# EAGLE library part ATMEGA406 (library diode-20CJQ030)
ATMEL's ATmega406 8bit AVR Microcontroller with 40KB In-System Programmable Flash Summary : Previous implementations of intelligent battery protection have typically required at least two chips to perform the various tasks required which include: voltage regulation, battery monitoring, battery protection, charge management, and communication with the host application. Often a third chip has been required to store parameters specific to the particular battery. Battery packs must shrink in size along with the other components of battery-powered applications. However, when accelerating this shrink, a 3-chip solution obviously creates a PCB space problem. The ATmega406 meets all the application's demands, reducing space, design complexity, and ultimately cost. It includes an AVR® microcontroller with dedicated analog to digital converters tailored for battery fuel gauging and voltage monitoring. Also included are stand-alone high voltage battery protection circuitry, a voltage regulator capable of running the chip on a supply varying from 4 to 25 Volts, integrated cell balancing FETs, and special high voltage I/O capable of controlling charge and discharge. Advanced analog design provides the ATmega406 with unmatched on-chip voltage reference accuracy, resulting in the first single-chip smart battery implementation on the market for 2 - 4 Li-ion cells. With 40 KB of self-programmable Flash program memory, the ATmega406 is capable of in-field firmware upgrades without the need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
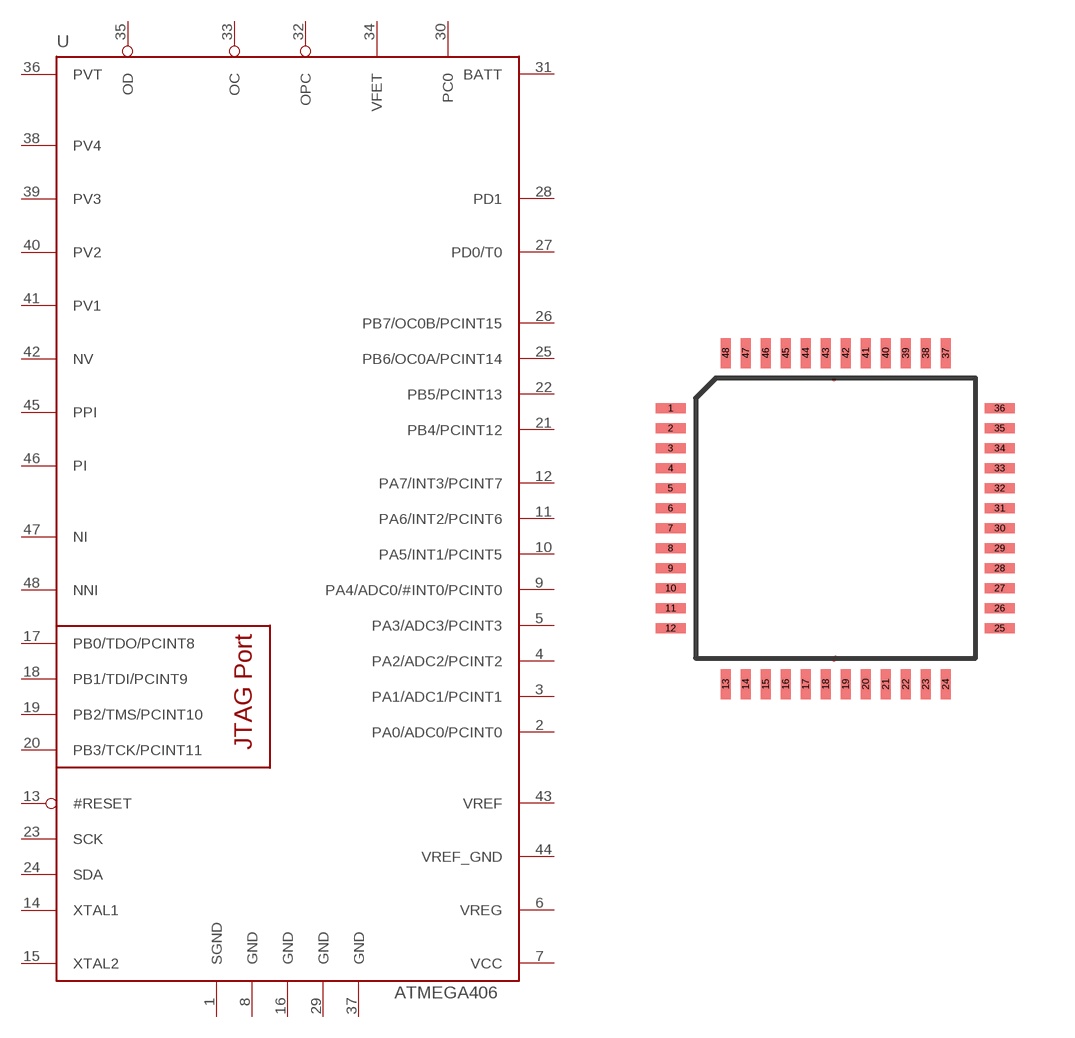
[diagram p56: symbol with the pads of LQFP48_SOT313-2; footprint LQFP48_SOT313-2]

Designator prefix U

## ATMEGA406  [LQFP48_SOT313-2]
1  SGND  pwr
2  PA0/ADC0/PCINT0
3  PA1/ADC1/PCINT1
4  PA2/ADC2/PCINT2
5  PA3/ADC3/PCINT3
6  VREG  out
7  VCC  pwr
8  GND  pwr
9  PA4/ADC0/#INT0/PCINT0
10  PA5/INT1/PCINT5
11  PA6/INT2/PCINT6
12  PA7/INT3/PCINT7
13  #RESET  in
14  XTAL1  in
15  XTAL2  in
16  GND  pwr
17  PB0/TDO/PCINT8
18  PB1/TDI/PCINT9
19  PB2/TMS/PCINT10
20  PB3/TCK/PCINT11
21  PB4/PCINT12
22  PB5/PCINT13
23  SCK
24  SDA
25  PB6/OC0A/PCINT14
26  PB7/OC0B/PCINT15
27  PD0/T0
28  PD1
29  GND  pwr
30  PC0  out
31  BATT  in
32  OPC  out
33  OC  out
34  VFET  pwr
35  OD  out
36  PVT  in
37  GND  pwr
38  PV4  in
39  PV3  in
40  PV2  in
41  PV1  in
42  NV  in
43  VREF  pwr
44  VREF_GND  pwr
45  PPI  in
46  PI  in
47  NI  in
48  NNI  in

## Footprint LQFP48_SOT313-2 (pad centres in mm)
LQFP48: plastic low profile quad flat package 48 leads body 7 x 7 x 1.4 mm
smd 0.75 x 0.25: 1 -4.125,2.75; 2 -4.125,2.25; 3 -4.125,1.75; 4 -4.125,1.25; 5 -4.125,0.75; 6 -4.125,0.25; 7 -4.125,-0.25; 8 -4.125,-0.75; 9 -4.125,-1.25; 10 -4.125,-1.75; 11 -4.125,-2.25; 12 -4.125,-2.75; 25 4.105,-2.75; 26 4.105,-2.25; 27 4.105,-1.75; 28 4.105,-1.25; 29 4.105,-0.75; 30 4.105,-0.25; 31 4.105,0.25; 32 4.105,0.75; 33 4.105,1.25; 34 4.105,1.75; 35 4.105,2.25; 36 4.105,2.75
smd 0.25 x 0.75: 13 -2.75,-4.155; 14 -2.25,-4.155; 15 -1.75,-4.155; 16 -1.25,-4.155; 17 -0.75,-4.155; 18 -0.25,-4.155; 19 0.25,-4.155; 20 0.75,-4.155; 21 1.25,-4.155; 22 1.75,-4.155; 23 2.25,-4.155; 24 2.75,-4.155; 37 2.75,4.125; 38 2.25,4.125; 39 1.75,4.125; 40 1.25,4.125; 41 0.75,4.125; 42 0.25,4.125; 43 -0.25,4.125; 44 -0.75,4.125; 45 -1.25,4.125; 46 -1.75,4.125; 47 -2.25,4.125; 48 -2.75,4.125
